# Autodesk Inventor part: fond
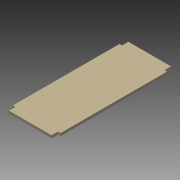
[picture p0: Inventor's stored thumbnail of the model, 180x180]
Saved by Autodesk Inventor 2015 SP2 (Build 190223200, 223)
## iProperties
Created: 2015-08
Part Number: fond
Material: Générique
Document SubType Name: Modeling
Designer: Dominique
Density: 1 g/cm^3
Appearance: Beige
Author: Dominique
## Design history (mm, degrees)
sketch "Esquisse1"
  geometry: L1 (3, 0)-(53, 0); L2 (56, 7.5)-(56, 132.5); L3 (53, 140)-(3, 140); L4 (0, 132.5)-(0, 7.5); L5 (3, 140)-(3, 132.5); L6 (3, 132.5)-(0, 132.5); L7 (53, 140)-(53, 132.5); L8 (53, 132.5)-(56, 132.5); L9 (3, 0)-(3, 7.5); L10 (3, 7.5)-(0, 7.5); L11 (53, 0)-(53, 7.5); L12 (53, 7.5)-(56, 7.5); 1 further point
  constraints: 24 end point, 3 point on line, 2 parallel, 1 horizontal, 1 perpendicular
extrude "Extrusion1" new body sketch "Esquisse1" distance "d7" = 3; taper "d8" = 0 deg
node "Solide1"
